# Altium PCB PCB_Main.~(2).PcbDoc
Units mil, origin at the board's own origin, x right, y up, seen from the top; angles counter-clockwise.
Board outline 6000 x 4000 mil, 2 copper layers (Top Layer, Bottom Layer); 1 components, 0 nets, 20 pads, 0 vias.
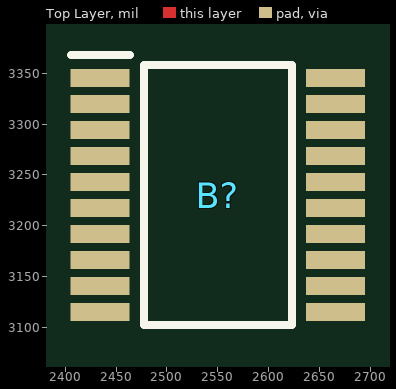
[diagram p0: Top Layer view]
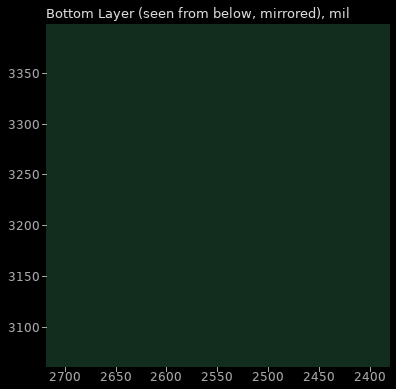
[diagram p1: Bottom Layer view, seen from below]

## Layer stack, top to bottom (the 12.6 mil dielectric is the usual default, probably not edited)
Top Solder: solder mask 0.4, Solder Resist, Dk 3.5
Top Layer: signal copper 1.4
Dielectric 1: dielectric 12.6, FR-4, Dk 4.8
Bottom Layer: signal copper 1.4
Bottom Solder: solder mask 0.4, Solder Resist, Dk 3.5

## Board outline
1000,1000 7000,1000 7000,5000 1000,5000

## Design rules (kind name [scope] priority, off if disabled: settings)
Clearance [All] p1: gap=10 ignorepadtopadclearanceinfootprint=FALSE
PolygonConnect [All] p1: connectstyle=Relief reliefconductorwidth=10 reliefentries=4 polygonreliefangle="90 Angle" airgapwidth=10
RoutingVias [All] p1: holewidth=28 width=50 viastyle="Through Hole" minholewidth=28 minwidth=50 maxholewidth=28 maxwidth=50
SolderMaskExpansion [All] p1: expansion=4 istentingtop=FALSE
Width [All] p1: maxlimit=10 minlimit=10 preferedwidth=10
30 further rules are at their usual default settings.

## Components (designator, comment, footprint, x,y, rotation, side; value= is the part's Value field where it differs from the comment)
B? "DRV8300DPWR" SOP65P640X120-20N 2550,3230 r0 top

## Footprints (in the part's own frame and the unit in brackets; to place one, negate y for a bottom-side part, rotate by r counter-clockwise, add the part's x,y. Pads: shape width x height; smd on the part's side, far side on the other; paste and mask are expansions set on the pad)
SOP65P640X120-20N [mm]
  rect 1.475x0.45 smd: 1(-2.938,2.925) 2(-2.938,2.275) 3(-2.938,1.625) 4(-2.938,0.975) 5(-2.938,0.325) 6(-2.938,-0.325) 7(-2.938,-0.975) 8(-2.938,-1.625) 9(-2.938,-2.275) 10(-2.938,-2.925) 11(2.938,-2.925) 12(2.938,-2.275) 13(2.938,-1.625) 14(2.938,-0.975) 15(2.938,-0.325) 16(2.938,0.325) 17(2.938,0.975) 18(2.938,1.625) 19(2.938,2.275) 20(2.938,2.925)
  silkscreen extent -3.67,-3.25 1.85,3.5

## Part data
B?: "Gate Drivers 100-V max simple 3-phase gate driver with bootstrap diodes 20-TSSOP -40 to 125", Manufacturer_Name="Texas Instruments", Mouser Part Number=595-DRV8300DPWR

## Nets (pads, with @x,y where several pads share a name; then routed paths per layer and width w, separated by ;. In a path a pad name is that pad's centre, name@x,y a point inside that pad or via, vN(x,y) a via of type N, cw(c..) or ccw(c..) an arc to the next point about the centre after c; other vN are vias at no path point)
pads on no net: B?.1 B?.2 B?.3 B?.4 B?.5 B?.6 B?.7 B?.8 B?.9 B?.10 B?.11 B?.12 B?.13 B?.14 B?.15 B?.16 B?.17 B?.18 B?.19 B?.20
